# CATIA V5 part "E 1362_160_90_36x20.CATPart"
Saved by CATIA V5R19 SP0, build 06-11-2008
Definition: E 1362_160_90_36x20
Nomenclature: E 1362_160_90_36x20
Description: PART-E 1362_160_90_36x20-DESC
Material "Steel": density 7860 kg/m3, Young's modulus 2e+11 Pa, Poisson ratio 0.266, thermal expansion 1.17e-05 1/K
Bounding box of the stored display mesh (mm): x -80 to 80, y -80 to 80, z -12 to 8
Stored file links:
  G:\UTB\Kombinované\Bakalářská práce\Catia\FORMA\E 1362_160_90_36x20.CATPart
  D:\Aplikace\CATIA\Nová složka\win_b64\startup\materials\Catalog.CATMaterial
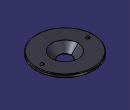
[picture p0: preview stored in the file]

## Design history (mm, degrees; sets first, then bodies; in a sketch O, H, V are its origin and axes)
Body1 "E 1362_160_90_36x20" (main body)
  Solid1: solid without history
